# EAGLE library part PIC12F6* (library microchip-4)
uPC nW 1k Program Flash memory 2x Timer Comparator 10b A/D converter/ 4xIN
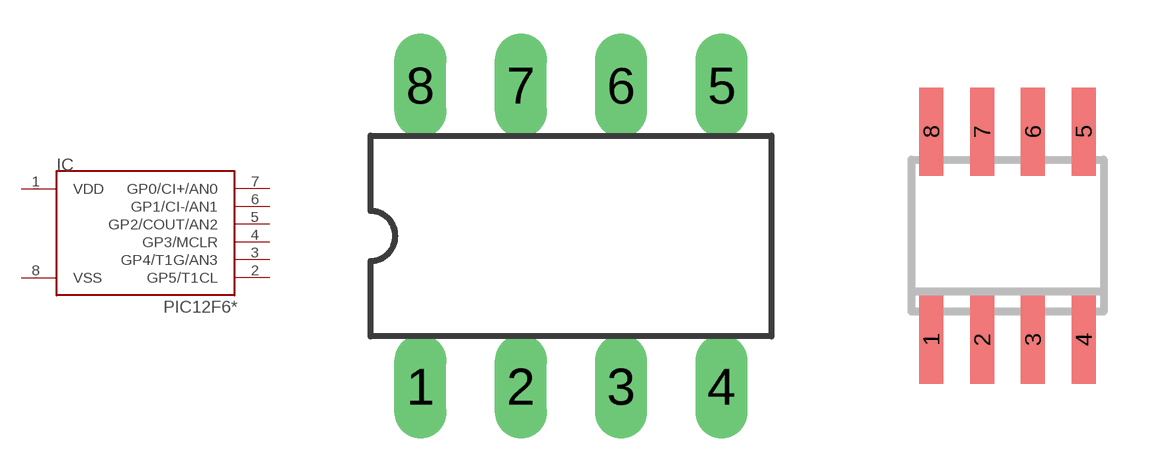
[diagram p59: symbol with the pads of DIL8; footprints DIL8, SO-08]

Designator prefix IC

## PIC12F629P, PIC12F675P  [DIL8]
1  VDD  pwr
2  GP5/T1CL
3  GP4/T1G/AN3
4  GP3/MCLR  in
5  GP2/COUT/AN2
6  GP1/CI-/AN1
7  GP0/CI+/AN0
8  VSS  pwr

## PIC12F629SN, PIC12F675SN  [SO-08]
Pads as for DIL8

## Footprint DIL8 (pad centres in mm)
Dual In Line package type P
drill 0.813 long: 1 -3.81,-3.81; 2 -1.27,-3.81; 3 1.27,-3.81; 4 3.81,-3.81; 5 3.81,3.81; 6 1.27,3.81; 7 -1.27,3.81; 8 -3.81,3.81

## Footprint SO-08 (pad centres in mm)
Small Outline Narrow Plastic Gull Wing 150-mil body, package type SN
smd 0.6 x 2.2: 1 -1.905,-2.6; 2 -0.635,-2.6; 3 0.635,-2.6; 4 1.905,-2.6; 5 1.905,2.6; 6 0.635,2.6; 7 -0.635,2.6; 8 -1.905,2.6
